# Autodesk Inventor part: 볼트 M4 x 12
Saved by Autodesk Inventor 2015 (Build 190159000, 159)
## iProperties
Created: 2025-08
Part Number: 볼트 M4 x 12
Material: 일반
Document SubType Name: Modeling
Designer: USER
Density: 1 g/cm^3
Appearance: 기본값
Author: USER
Author: jhkim
Description: 6각머리 태핑 나사
Creation Date: 2025-08-05
Sending System: Autodesk Inventor 2026
Preprocessor: ST-DEVELOPER v20.1
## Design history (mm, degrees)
node "볼트 M4 x 121"
body "Solid1"
node "기준1"
